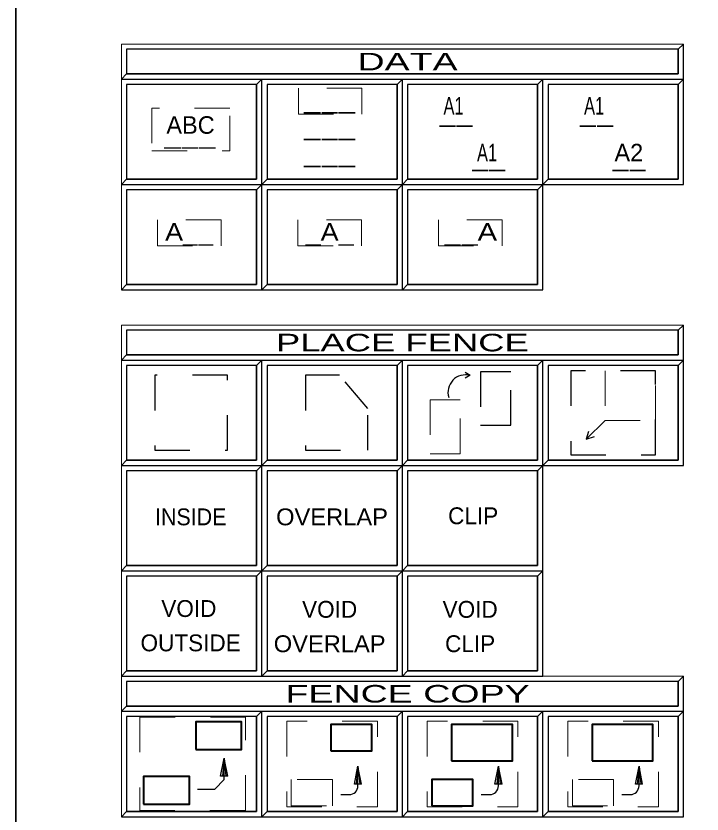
# Model space of a CAD drawing. Extents: x 95906.8 to 95923.6, y 90964.8 to 90972.8.
# Drawn here: x 95906.832 to 95908.785, y 90967.269 to 90969.542 of the extents above; entities that cross this region are included whole.
import ezdxf
from ezdxf.enums import TextEntityAlignment as Align

# ---------------------------------------------------------------- set-up
doc = ezdxf.new("R2010")
doc.units = 0
doc.header["$LTSCALE"] = 0.019
doc.linetypes.add('DOTTED', pattern=[1.5, 0.3, -1.2])
doc.linetypes.add('MEDIUM_DASHED', pattern=[4.5, 3, -1.5])
for name, color, linetype, lineweight in [('11', 7, 'Continuous', 25), ('12', 7, 'Continuous', 25), ('18', 7, 'Continuous', 25), ('2', 7, 'Continuous', 13), ('3', 7, 'Continuous', 25), ('6', 7, 'Continuous', 25), ('7', 7, 'Continuous', 35)]:
    doc.layers.add(name, color=color, linetype=linetype, lineweight=lineweight)

msp = doc.modelspace()

# ---------------------------------------------------------------- linework, layer by layer
at = {"layer": '11'}
for points in [[(95907.5473, 90969.0767), (95907.9173, 90969.0767), (95907.9173, 90969.3467), (95907.5473, 90969.3467)], [(95907.9473, 90969.0767), (95908.3173, 90969.0767), (95908.3173, 90969.3467), (95907.9473, 90969.3467)], [(95908.3473, 90969.0767), (95908.7173, 90969.0767), (95908.7173, 90969.3467), (95908.3473, 90969.3467)], [(95907.1473, 90968.7767), (95907.5173, 90968.7767), (95907.5173, 90969.0467), (95907.1473, 90969.0467)], [(95907.5473, 90968.7767), (95907.9173, 90968.7767), (95907.9173, 90969.0467), (95907.5473, 90969.0467)], [(95907.9473, 90968.7767), (95908.3173, 90968.7767), (95908.3173, 90969.0467), (95907.9473, 90969.0467)], [(95907.5473, 90968.2767), (95907.9173, 90968.2767), (95907.9173, 90968.5467), (95907.5473, 90968.5467)], [(95907.9473, 90968.2767), (95908.3173, 90968.2767), (95908.3173, 90968.5467), (95907.9473, 90968.5467)], [(95908.3473, 90968.2767), (95908.7173, 90968.2767), (95908.7173, 90968.5467), (95908.3473, 90968.5467)], [(95907.1473, 90967.9767), (95907.5173, 90967.9767), (95907.5173, 90968.2467), (95907.1473, 90968.2467)], [(95907.5473, 90967.9767), (95907.9173, 90967.9767), (95907.9173, 90968.2467), (95907.5473, 90968.2467)], [(95907.9473, 90967.9767), (95908.3173, 90967.9767), (95908.3173, 90968.2467), (95907.9473, 90968.2467)], [(95907.1473, 90967.6767), (95907.5173, 90967.6767), (95907.5173, 90967.9467), (95907.1473, 90967.9467)], [(95907.5473, 90967.6767), (95907.9173, 90967.6767), (95907.9173, 90967.9467), (95907.5473, 90967.9467)], [(95907.9473, 90967.6767), (95908.3173, 90967.6767), (95908.3173, 90967.9467), (95907.9473, 90967.9467)], [(95907.1473, 90967.2767), (95907.5173, 90967.2767), (95907.5173, 90967.5467), (95907.1473, 90967.5467)], [(95907.5473, 90967.2767), (95907.9173, 90967.2767), (95907.9173, 90967.5467), (95907.5473, 90967.5467)], [(95907.9473, 90967.2767), (95908.3173, 90967.2767), (95908.3173, 90967.5467), (95907.9473, 90967.5467)], [(95908.3473, 90967.2767), (95908.7173, 90967.2767), (95908.7173, 90967.5467), (95908.3473, 90967.5467)]]:
    msp.add_lwpolyline(points, close=True, dxfattribs=at)
at = {"layer": '12'}
for points in [[(95907.1473, 90969.0767), (95907.5173, 90969.0767), (95907.5173, 90969.3467), (95907.1473, 90969.3467)], [(95907.1473, 90968.2767), (95907.5173, 90968.2767), (95907.5173, 90968.5467), (95907.1473, 90968.5467)]]:
    msp.add_lwpolyline(points, close=True, dxfattribs=at)
at = {"layer": '18'}
for points in [[(95907.1473, 90969.3767), (95908.7173, 90969.3767), (95908.7173, 90969.4467), (95907.1473, 90969.4467)], [(95907.1473, 90968.5767), (95908.7173, 90968.5767), (95908.7173, 90968.6467), (95907.1473, 90968.6467)], [(95907.1473, 90967.5767), (95908.7173, 90967.5767), (95908.7173, 90967.6467), (95907.1473, 90967.6467)]]:
    msp.add_lwpolyline(points, close=True, dxfattribs=at)
at = {"layer": '2'}
for points in [[(95907.1323, 90969.4617), (95907.1323, 90969.3617), (95907.1473, 90969.3767), (95907.1473, 90969.4467), (95908.7173, 90969.4467), (95908.7323, 90969.4617)], [(95907.1323, 90969.3617), (95907.1323, 90969.0617), (95907.1473, 90969.0767), (95907.1473, 90969.3467), (95907.5173, 90969.3467), (95907.5323, 90969.3617)], [(95907.5323, 90969.3617), (95907.5323, 90969.0617), (95907.5473, 90969.0767), (95907.5473, 90969.3467), (95907.9173, 90969.3467), (95907.9323, 90969.3617)], [(95907.9323, 90969.3617), (95907.9323, 90969.0617), (95907.9473, 90969.0767), (95907.9473, 90969.3467), (95908.3173, 90969.3467), (95908.3323, 90969.3617)], [(95908.3323, 90969.3617), (95908.3323, 90969.0617), (95908.3473, 90969.0767), (95908.3473, 90969.3467), (95908.7173, 90969.3467), (95908.7323, 90969.3617)], [(95907.1323, 90969.0617), (95907.1323, 90968.7617), (95907.1473, 90968.7767), (95907.1473, 90969.0467), (95907.5173, 90969.0467), (95907.5323, 90969.0617)], [(95907.5323, 90969.0617), (95907.5323, 90968.7617), (95907.5473, 90968.7767), (95907.5473, 90969.0467), (95907.9173, 90969.0467), (95907.9323, 90969.0617)], [(95907.9323, 90969.0617), (95907.9323, 90968.7617), (95907.9473, 90968.7767), (95907.9473, 90969.0467), (95908.3173, 90969.0467), (95908.3323, 90969.0617)], [(95907.1323, 90968.6617), (95907.1323, 90968.5617), (95907.1473, 90968.5767), (95907.1473, 90968.6467), (95908.7173, 90968.6467), (95908.7323, 90968.6617)], [(95907.1323, 90968.5617), (95907.1323, 90968.2617), (95907.1473, 90968.2767), (95907.1473, 90968.5467), (95907.5173, 90968.5467), (95907.5323, 90968.5617)], [(95907.5323, 90968.5617), (95907.5323, 90968.2617), (95907.5473, 90968.2767), (95907.5473, 90968.5467), (95907.9173, 90968.5467), (95907.9323, 90968.5617)], [(95907.9323, 90968.5617), (95907.9323, 90968.2617), (95907.9473, 90968.2767), (95907.9473, 90968.5467), (95908.3173, 90968.5467), (95908.3323, 90968.5617)], [(95908.3323, 90968.5617), (95908.3323, 90968.2617), (95908.3473, 90968.2767), (95908.3473, 90968.5467), (95908.7173, 90968.5467), (95908.7323, 90968.5617)], [(95907.1323, 90968.2617), (95907.1323, 90967.9617), (95907.1473, 90967.9767), (95907.1473, 90968.2467), (95907.5173, 90968.2467), (95907.5323, 90968.2617)], [(95907.5323, 90968.2617), (95907.5323, 90967.9617), (95907.5473, 90967.9767), (95907.5473, 90968.2467), (95907.9173, 90968.2467), (95907.9323, 90968.2617)], [(95907.9323, 90968.2617), (95907.9323, 90967.9617), (95907.9473, 90967.9767), (95907.9473, 90968.2467), (95908.3173, 90968.2467), (95908.3323, 90968.2617)], [(95907.1323, 90967.9617), (95907.1323, 90967.6617), (95907.1473, 90967.6767), (95907.1473, 90967.9467), (95907.5173, 90967.9467), (95907.5323, 90967.9617)], [(95907.5323, 90967.9617), (95907.5323, 90967.6617), (95907.5473, 90967.6767), (95907.5473, 90967.9467), (95907.9173, 90967.9467), (95907.9323, 90967.9617)], [(95907.9323, 90967.9617), (95907.9323, 90967.6617), (95907.9473, 90967.6767), (95907.9473, 90967.9467), (95908.3173, 90967.9467), (95908.3323, 90967.9617)], [(95907.1323, 90967.6617), (95907.1323, 90967.5617), (95907.1473, 90967.5767), (95907.1473, 90967.6467), (95908.7173, 90967.6467), (95908.7323, 90967.6617)], [(95907.1323, 90967.5617), (95907.1323, 90967.2617), (95907.1473, 90967.2767), (95907.1473, 90967.5467), (95907.5173, 90967.5467), (95907.5323, 90967.5617)], [(95907.5323, 90967.5617), (95907.5323, 90967.2617), (95907.5473, 90967.2767), (95907.5473, 90967.5467), (95907.9173, 90967.5467), (95907.9323, 90967.5617)], [(95907.9323, 90967.5617), (95907.9323, 90967.2617), (95907.9473, 90967.2767), (95907.9473, 90967.5467), (95908.3173, 90967.5467), (95908.3323, 90967.5617)], [(95908.3323, 90967.5617), (95908.3323, 90967.2617), (95908.3473, 90967.2767), (95908.3473, 90967.5467), (95908.7173, 90967.5467), (95908.7323, 90967.5617)]]:
    msp.add_lwpolyline(points, close=True, dxfattribs=at)
at = {"layer": '3'}
for points in [[(95907.1323, 90969.3617), (95908.7323, 90969.3617), (95908.7323, 90969.4617), (95908.7173, 90969.4467), (95908.7173, 90969.3767), (95907.1473, 90969.3767)], [(95907.1323, 90969.0617), (95907.5323, 90969.0617), (95907.5323, 90969.3617), (95907.5173, 90969.3467), (95907.5173, 90969.0767), (95907.1473, 90969.0767)], [(95907.5323, 90969.0617), (95907.9323, 90969.0617), (95907.9323, 90969.3617), (95907.9173, 90969.3467), (95907.9173, 90969.0767), (95907.5473, 90969.0767)], [(95907.9323, 90969.0617), (95908.3323, 90969.0617), (95908.3323, 90969.3617), (95908.3173, 90969.3467), (95908.3173, 90969.0767), (95907.9473, 90969.0767)], [(95908.3323, 90969.0617), (95908.7323, 90969.0617), (95908.7323, 90969.3617), (95908.7173, 90969.3467), (95908.7173, 90969.0767), (95908.3473, 90969.0767)], [(95907.1323, 90968.7617), (95907.5323, 90968.7617), (95907.5323, 90969.0617), (95907.5173, 90969.0467), (95907.5173, 90968.7767), (95907.1473, 90968.7767)], [(95907.5323, 90968.7617), (95907.9323, 90968.7617), (95907.9323, 90969.0617), (95907.9173, 90969.0467), (95907.9173, 90968.7767), (95907.5473, 90968.7767)], [(95907.9323, 90968.7617), (95908.3323, 90968.7617), (95908.3323, 90969.0617), (95908.3173, 90969.0467), (95908.3173, 90968.7767), (95907.9473, 90968.7767)], [(95907.1323, 90968.5617), (95908.7323, 90968.5617), (95908.7323, 90968.6617), (95908.7173, 90968.6467), (95908.7173, 90968.5767), (95907.1473, 90968.5767)], [(95907.1323, 90968.2617), (95907.5323, 90968.2617), (95907.5323, 90968.5617), (95907.5173, 90968.5467), (95907.5173, 90968.2767), (95907.1473, 90968.2767)], [(95907.5323, 90968.2617), (95907.9323, 90968.2617), (95907.9323, 90968.5617), (95907.9173, 90968.5467), (95907.9173, 90968.2767), (95907.5473, 90968.2767)], [(95907.9323, 90968.2617), (95908.3323, 90968.2617), (95908.3323, 90968.5617), (95908.3173, 90968.5467), (95908.3173, 90968.2767), (95907.9473, 90968.2767)], [(95908.3323, 90968.2617), (95908.7323, 90968.2617), (95908.7323, 90968.5617), (95908.7173, 90968.5467), (95908.7173, 90968.2767), (95908.3473, 90968.2767)], [(95907.1323, 90967.9617), (95907.5323, 90967.9617), (95907.5323, 90968.2617), (95907.5173, 90968.2467), (95907.5173, 90967.9767), (95907.1473, 90967.9767)], [(95907.5323, 90967.9617), (95907.9323, 90967.9617), (95907.9323, 90968.2617), (95907.9173, 90968.2467), (95907.9173, 90967.9767), (95907.5473, 90967.9767)], [(95907.9323, 90967.9617), (95908.3323, 90967.9617), (95908.3323, 90968.2617), (95908.3173, 90968.2467), (95908.3173, 90967.9767), (95907.9473, 90967.9767)], [(95907.1323, 90967.6617), (95907.5323, 90967.6617), (95907.5323, 90967.9617), (95907.5173, 90967.9467), (95907.5173, 90967.6767), (95907.1473, 90967.6767)], [(95907.5323, 90967.6617), (95907.9323, 90967.6617), (95907.9323, 90967.9617), (95907.9173, 90967.9467), (95907.9173, 90967.6767), (95907.5473, 90967.6767)], [(95907.9323, 90967.6617), (95908.3323, 90967.6617), (95908.3323, 90967.9617), (95908.3173, 90967.9467), (95908.3173, 90967.6767), (95907.9473, 90967.6767)], [(95907.1323, 90967.5617), (95908.7323, 90967.5617), (95908.7323, 90967.6617), (95908.7173, 90967.6467), (95908.7173, 90967.5767), (95907.1473, 90967.5767)], [(95907.1323, 90967.2617), (95907.5323, 90967.2617), (95907.5323, 90967.5617), (95907.5173, 90967.5467), (95907.5173, 90967.2767), (95907.1473, 90967.2767)], [(95907.5323, 90967.2617), (95907.9323, 90967.2617), (95907.9323, 90967.5617), (95907.9173, 90967.5467), (95907.9173, 90967.2767), (95907.5473, 90967.2767)], [(95907.9323, 90967.2617), (95908.3323, 90967.2617), (95908.3323, 90967.5617), (95908.3173, 90967.5467), (95908.3173, 90967.2767), (95907.9473, 90967.2767)], [(95908.3323, 90967.2617), (95908.7323, 90967.2617), (95908.7323, 90967.5617), (95908.7173, 90967.5467), (95908.7173, 90967.2767), (95908.3473, 90967.2767)]]:
    msp.add_lwpolyline(points, close=True, dxfattribs=at)
at = {"layer": '6'}
for p, q in [((95908.5093, 90968.3899), (95908.4558, 90968.3364)), ((95907.4251, 90967.3769), (95907.4251, 90967.4281)), ((95907.4251, 90967.4281), (95907.4299, 90967.3769)), ((95907.8059, 90967.3495), (95907.8059, 90967.4052)), ((95907.8059, 90967.354), (95907.8059, 90967.4052)), ((95907.8059, 90967.4052), (95907.8107, 90967.354)), ((95908.2059, 90967.3495), (95908.2059, 90967.4052)), ((95908.2059, 90967.354), (95908.2059, 90967.4052)), ((95908.2059, 90967.4052), (95908.2107, 90967.354)), ((95908.6059, 90967.3495), (95908.6059, 90967.4052)), ((95908.6059, 90967.354), (95908.6059, 90967.4052)), ((95908.6059, 90967.4052), (95908.6107, 90967.354)), ((95907.7569, 90967.3245), (95907.7809, 90967.3245)), ((95908.1569, 90967.3245), (95908.1809, 90967.3245)), ((95908.5569, 90967.3245), (95908.5809, 90967.3245))]:
    msp.add_line(p, q, dxfattribs=at)
at = {"layer": '6', "linetype": 'MEDIUM_DASHED', "lineweight": 13}
for points in [[(95907.6362, 90969.2625), (95907.8173, 90969.2625), (95907.8173, 90969.3363), (95907.6362, 90969.3363)], [(95907.2194, 90969.1576), (95907.4409, 90969.1576), (95907.4409, 90969.2791), (95907.2194, 90969.2791)], [(95907.235, 90968.887), (95907.4161, 90968.887), (95907.4161, 90968.9608), (95907.235, 90968.9608)], [(95907.635, 90968.887), (95907.8161, 90968.887), (95907.8161, 90968.9608), (95907.635, 90968.9608)], [(95908.035, 90968.887), (95908.2161, 90968.887), (95908.2161, 90968.9608), (95908.035, 90968.9608)], [(95907.6161, 90967.2929), (95907.7332, 90967.2929), (95907.7332, 90967.3672), (95907.6161, 90967.3672)], [(95908.4161, 90967.2929), (95908.5332, 90967.2929), (95908.5332, 90967.3672), (95908.4161, 90967.3672)]]:
    msp.add_lwpolyline(points, close=True, dxfattribs=at)
at = {"layer": '6', "linetype": 'DOTTED'}
for points in [[(95907.2274, 90968.305), (95907.4344, 90968.305), (95907.4344, 90968.5184), (95907.2274, 90968.5184)], [(95907.6564, 90968.305), (95907.8344, 90968.305), (95907.8344, 90968.4236), (95907.7536, 90968.5184), (95907.6564, 90968.5184)]]:
    msp.add_lwpolyline(points, close=True, dxfattribs=at)
at = {"layer": '6'}
for points in [[(95908.1106, 90968.5274), (95908.1248, 90968.5184), (95908.1106, 90968.5106)], [(95908.4623, 90968.3583), (95908.4558, 90968.3364), (95908.479, 90968.3441)], [(95907.3487, 90967.3404), (95907.3982, 90967.3404), (95907.4251, 90967.3673), (95907.4251, 90967.4281)], [(95907.4353, 90967.3769), (95907.4149, 90967.3769), (95907.4251, 90967.4281)], [(95907.4353, 90967.3769), (95907.4251, 90967.4281), (95907.4201, 90967.3769)], [(95907.8161, 90967.354), (95907.7957, 90967.354), (95907.8059, 90967.4052)], [(95907.8161, 90967.354), (95907.8059, 90967.4052), (95907.8009, 90967.354)], [(95908.2161, 90967.354), (95908.1957, 90967.354), (95908.2059, 90967.4052)], [(95908.2161, 90967.354), (95908.2059, 90967.4052), (95908.2009, 90967.354)], [(95908.6161, 90967.354), (95908.5957, 90967.354), (95908.6059, 90967.4052)], [(95908.6161, 90967.354), (95908.6059, 90967.4052), (95908.6009, 90967.354)]]:
    msp.add_lwpolyline(points, dxfattribs=at)
at = {"layer": '6', "linetype": 'MEDIUM_DASHED'}
for points in [[(95908.1545, 90968.3764), (95908.2409, 90968.3764), (95908.2409, 90968.5287), (95908.1545, 90968.5287)], [(95908.4119, 90968.2925), (95908.6533, 90968.2925), (95908.6533, 90968.5313), (95908.4119, 90968.5313)]]:
    msp.add_lwpolyline(points, close=True, dxfattribs=at)
at = {"layer": '6', "linetype": 'DOTTED', "lineweight": 13}
for points in [[(95908.6533, 90968.5313), (95908.5093, 90968.5313), (95908.5093, 90968.3899), (95908.6533, 90968.3899)], [(95908.0112, 90968.2951), (95908.0964, 90968.2951), (95908.0964, 90968.4487), (95908.0112, 90968.4487)], [(95907.1845, 90967.2796), (95907.4859, 90967.2796), (95907.4859, 90967.545), (95907.1845, 90967.545)], [(95907.6029, 90967.2893), (95907.8611, 90967.2893), (95907.8611, 90967.5332), (95907.6029, 90967.5332)], [(95908.0029, 90967.2893), (95908.2611, 90967.2893), (95908.2611, 90967.5332), (95908.0029, 90967.5332)], [(95908.4029, 90967.2893), (95908.6611, 90967.2893), (95908.6611, 90967.5332), (95908.4029, 90967.5332)]]:
    msp.add_lwpolyline(points, close=True, dxfattribs=at)
at = {"layer": '6', "lineweight": 40}
for points in [[(95907.3442, 90967.4528), (95907.4747, 90967.4528), (95907.4747, 90967.5315), (95907.3442, 90967.5315)], [(95907.7284, 90967.4495), (95907.8455, 90967.4495), (95907.8455, 90967.5238), (95907.7284, 90967.5238)], [(95908.0724, 90967.421), (95908.2455, 90967.421), (95908.2455, 90967.5238), (95908.0724, 90967.5238)], [(95908.4724, 90967.421), (95908.6455, 90967.421), (95908.6455, 90967.5238), (95908.4724, 90967.5238)], [(95907.1957, 90967.2977), (95907.3262, 90967.2977), (95907.3262, 90967.3764), (95907.1957, 90967.3764)], [(95908.0161, 90967.2929), (95908.1332, 90967.2929), (95908.1332, 90967.3672), (95908.0161, 90967.3672)]]:
    msp.add_lwpolyline(points, close=True, dxfattribs=at)
at = {"layer": '6'}
for centre, radius, start, end in [((95908.1124, 90968.4695), 0.0504, 75.7794, 196.623), ((95907.7809, 90967.3495), 0.025, 270, 0), ((95908.1809, 90967.3495), 0.025, 270, 0), ((95908.5809, 90967.3495), 0.025, 270, 0)]:
    msp.add_arc(centre, radius, start, end, dxfattribs=at)
at = {"layer": '7'}
msp.add_lwpolyline([(95906.8323, 90972.7617), (95918.8323, 90972.7617), (95918.8323, 90964.7617), (95906.8323, 90964.7617)], close=True, dxfattribs=at)

# ---------------------------------------------------------------- texts
at = {"layer": '6'}
for s, height, width, p in [('A1', 0.04999, 0.7, (95908.078, 90969.261)), ('A1', 0.04999, 0.7, (95908.4781, 90969.261)), ('___', 0.04999, 1.3, (95907.7253, 90969.2779)), ('__', 0.04999, 1.25, (95908.085, 90969.2398)), ('__', 0.04999, 1.25, (95908.485, 90969.2398)), ('___', 0.04999, 1.3, (95907.7253, 90969.2017)), ('A1', 0.04999, 0.7, (95908.1733, 90969.1276)), ('___', 0.04999, 1.3, (95907.3274, 90969.1779)), ('___', 0.04999, 1.3, (95907.7253, 90969.1255)), ('__', 0.04999, 1.25, (95908.1779, 90969.1136)), ('__', 0.04999, 1.25, (95908.5779, 90969.1136)), ('A__', 0.04999, 1.15, (95907.3252, 90968.9017)), ('_A_', 0.04999, 1.15, (95907.7252, 90968.9017)), ('__A', 0.04999, 1.25, (95908.1277, 90968.9017)), ('INSIDE', 0.048, 0.95, (95907.3298, 90968.0914)), ('OVERLAP', 0.048, 1.05, (95907.732, 90968.0914)), ('OVERLAP', 0.048, 1.05, (95907.7253, 90967.7301))]:
    msp.add_text(s, height=height, dxfattribs=dict(at, width=width)).set_placement(p, align=Align.CENTER)
for s, height, p in [('ABC', 0.04999, (95907.3292, 90969.2062)), ('A2', 0.04999, (95908.5769, 90969.1276)), ('CLIP', 0.048, (95908.1338, 90968.0945)), ('VOID', 0.048, (95907.3245, 90967.8304)), ('VOID', 0.048, (95907.7252, 90967.8281)), ('VOID', 0.048, (95908.1252, 90967.828)), ('OUTSIDE', 0.048, (95907.3295, 90967.7326)), ('CLIP', 0.048, (95908.1252, 90967.7302))]:
    msp.add_text(s, height=height, dxfattribs=at).set_placement(p, align=Align.CENTER)
at = {"layer": '7'}
for s, width, p in [('          DATA         ', 1.6, (95907.9322, 90969.3867)), ('      PLACE FENCE      ', 1.55, (95907.9322, 90968.5867)), ('       FENCE COPY      ', 1.6, (95907.9322, 90967.5867))]:
    msp.add_text(s, height=0.04999, dxfattribs=dict(at, width=width)).set_placement(p, align=Align.CENTER)

doc.saveas('drawing.dxf')
